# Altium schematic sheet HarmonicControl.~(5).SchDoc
size A
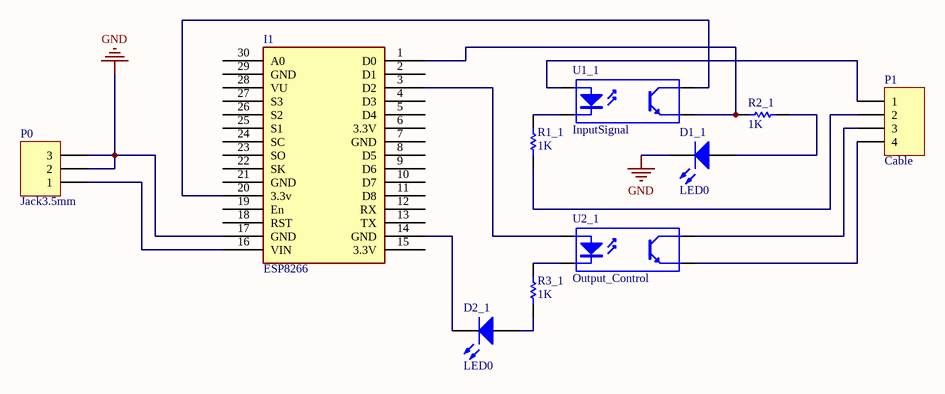
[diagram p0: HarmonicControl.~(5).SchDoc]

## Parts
D1_1  LED0  [LED-0]
D2_1  LED0  [LED-0]
I1  ESP8266  [ESP8266_Node_MCU_V3]
P0  Jack3.5mm  [HDR1X3]
P1  Cable  [HDR1X4]
R1_1  value 1K  [AXIAL-0.3]  (hidden comment: Res1)
R2_1  value 1K  [AXIAL-0.3]  (hidden comment: Res1)
R3_1  value 1K  [AXIAL-0.3]  (hidden comment: Res1)
U1_1  InputSignal  [DIP-4]
U2_1  Output_Control  [DIP-4]

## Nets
GND: D1_1.2(K) I1.17(GND) P0.2 P0.3
NetD1_1_1: D1_1.1(A) R2_1.2
NetD2_1_1: D2_1.1(A) R3_1.1
NetD2_1_2: D2_1.2(K) I1.14(GND)
NetI1_1: I1.1(D0) R2_1.1 U1_1.3(E)
NetI1_3: I1.3(D2) U2_1.1(A)
NetI1_16: I1.16(VIN) P0.1
NetI1_20: I1.20(3.3v) U1_1.4(C)
NetP1_1: P1.1 U1_1.1(A)
NetP1_2: P1.2 R1_1.1
NetP1_3: P1.3 U2_1.4(C)
NetP1_4: P1.4 U2_1.3(E)
NetR1_1_2: R1_1.2 U1_1.2(K)
NetR3_1_2: R3_1.2 U2_1.2(K)

Not connected (* = marked no-connect by the designer): I1 2(D1) 4(D3) 5(D4) 6(3.3V) 7(GND) 8(D5) 9(D6) 10(D7) 11(D8) 12(RX) 13(TX) 15(3.3V) 18(RST) 19(En) 21(GND) 22(SK) 23(SO) 24(SC) 25(S1) 26(S2) 27(S3) 28(VU) 29(GND) 30(A0)

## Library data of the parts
D1_1 D2_1 = LED0: Typical INFRARED GaAs LED
I1 = ESP8266_Node_MCU_V3
P0 = Header 3: Header, 3-Pin
P1 = Header 4: Header, 4-Pin
R1_1 R2_1 R3_1 = Res1: Resistor
U1_1 U2_1 = Optoisolator1: 4-Pin Phototransistor Optocoupler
